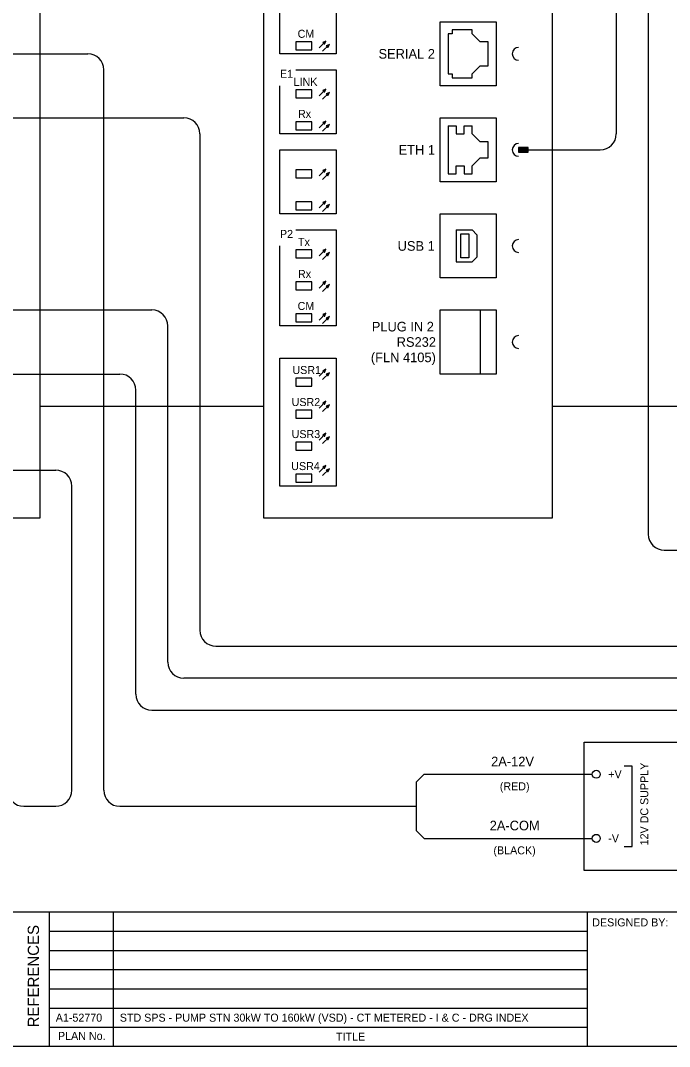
# Model space of a CAD drawing. Extents: x 0 to 841, y 0 to 594.
# Drawn here: x 204 to 406.6, y 15 to 335.4 of the extents above; entities that cross this region are included whole.
import ezdxf

# ---------------------------------------------------------------- set-up
doc = ezdxf.new("R2010")
doc.units = 0
for name, color, linetype in [('A1BORDER', 7, 'Continuous'), ('Level 1', 7, 'Continuous'), ('Level 10', 7, 'Continuous'), ('Level 5', 7, 'Continuous')]:
    doc.layers.add(name, color=color, linetype=linetype)

msp = doc.modelspace()

# ---------------------------------------------------------------- linework, layer by layer
at = {"layer": 'A1BORDER'}
for p, q in [((28, 57), (829, 57)), ((213, 15), (213, 57)), ((233, 15), (233, 57)), ((381, 15), (381, 57)), ((213, 51), (381, 51)), ((213, 45), (381, 45)), ((213, 39), (381, 39)), ((213, 33), (381, 33)), ((213, 27), (381, 27)), ((213, 21), (381, 21)), ((829, 15), (28, 15))]:
    msp.add_line(p, q, dxfattribs=at)
at = {"layer": 'Level 1'}
for p, q in [((390, 560), (390, 300)), ((400, 390), (400, 175)), ((337.5, 331.25), (337.5, 318.75)), ((338.75, 331.25), (337.5, 331.25)), ((345, 332.5), (338.75, 332.5)), ((338.75, 332.5), (338.75, 331.25)), ((345, 331.25), (345, 332.5)), ((345, 331.25), (347.5, 328.75)), ((350, 328.75), (347.5, 328.75)), ((350, 321.25), (350, 328.75)), ((197.5, 325), (225, 325)), ((345, 318.75), (347.5, 321.25)), ((347.5, 321.25), (350, 321.25)), ((230, 95), (230, 320)), ((337.5, 318.75), (338.75, 318.75)), ((338.75, 318.75), (338.75, 317.5)), ((338.75, 317.5), (345, 317.5)), ((345, 317.5), (345, 318.75)), ((197.5, 305), (255, 305)), ((337.5, 302.5), (337.5, 287.5)), ((337.5, 302.5), (340, 302.5)), ((340, 302.5), (340, 300)), ((342.5, 300), (342.5, 302.5)), ((342.5, 302.5), (345, 302.5)), ((345, 300), (345, 302.5)), ((260, 300), (260, 145)), ((340, 300), (342.5, 300)), ((345, 300), (347.5, 297.5)), ((350, 297.5), (347.5, 297.5)), ((350, 292.5), (350, 297.5)), ((362.5, 295), (385, 295)), ((345, 290), (347.5, 292.5)), ((347.5, 292.5), (350, 292.5)), ((340, 287.5), (340, 290)), ((340, 290), (342.5, 290)), ((342.5, 290), (342.5, 287.5)), ((345, 287.5), (345, 290)), ((337.5, 287.5), (340, 287.5)), ((342.5, 287.5), (345, 287.5)), ((340, 270), (340, 260)), ((340, 270), (345, 270)), ((345, 270), (346.5, 268.5)), ((346.5, 268.5), (346.5, 261.5)), ((340, 260), (345, 260)), ((345, 260), (346.5, 261.5)), ((197.5, 245), (245, 245)), ((347.5, 245), (347.5, 225)), ((250, 135), (250, 240)), ((197.5, 225), (235, 225)), ((240, 125), (240, 220)), ((210, 215), (280, 215)), ((370, 215), (410, 215)), ((197.5, 195), (215, 195)), ((220, 95), (220, 190)), ((405, 170), (595, 170)), ((265, 140), (610, 140)), ((645, 130), (255, 130)), ((245, 120), (725, 120)), ((330, 100), (327.5, 97.5)), ((330, 100), (382.5, 100)), ((327.5, 97.5), (327.5, 82.5)), ((205, 90), (215, 90)), ((215, 90), (215, 90)), ((235, 90), (327.51, 90)), ((330, 80), (327.5, 82.5)), ((330, 80), (382.5, 80))]:
    msp.add_line(p, q, dxfattribs=at)
for points in [[(130, 520), (210, 520), (210, 180), (130, 180)], [(280, 520), (370, 520), (370, 180), (280, 180)], [(335, 335), (352.5, 335), (352.5, 315), (335, 315)], [(295, 328.75), (290, 328.75), (290, 326.25), (295, 326.25)], [(295, 313.75), (290, 313.75), (290, 311.25), (295, 311.25)], [(335, 305), (352.5, 305), (352.5, 285), (335, 285)], [(295, 303.75), (290, 303.75), (290, 301.25), (295, 301.25)], [(285, 295), (302.5, 295), (302.5, 275), (285, 275)], [(295, 288.75), (290, 288.75), (290, 286.25), (295, 286.25)], [(295, 278.75), (290, 278.75), (290, 276.25), (295, 276.25)], [(335, 275), (352.5, 275), (352.5, 255), (335, 255)], [(341.5, 268.75), (344, 268.75), (344, 261.25), (341.5, 261.25)], [(295, 263.75), (290, 263.75), (290, 261.25), (295, 261.25)], [(295, 253.75), (290, 253.75), (290, 251.25), (295, 251.25)], [(295, 243.75), (290, 243.75), (290, 241.25), (295, 241.25)], [(335, 245), (352.5, 245), (352.5, 225), (335, 225)], [(285, 230), (302.5, 230), (302.5, 190), (285, 190)], [(295, 223.75), (290, 223.75), (290, 221.25), (295, 221.25)], [(295, 213.75), (290, 213.75), (290, 211.25), (295, 211.25)], [(295, 203.75), (290, 203.75), (290, 201.25), (295, 201.25)], [(295, 193.75), (290, 193.75), (290, 191.25), (295, 191.25)], [(380, 110), (455, 110), (455, 70), (380, 70)]]:
    msp.add_lwpolyline(points, close=True, dxfattribs=at)
for points in [[(290, 355), (302.5, 355), (302.5, 325), (285, 325), (285, 350)], [(290, 320), (302.5, 320), (302.5, 300), (285, 300), (285, 315)], [(290, 270), (302.5, 270), (302.5, 240), (285, 240), (285, 265)], [(392.5, 77.5), (395, 77.5), (395, 102.5), (392.5, 102.5)]]:
    msp.add_lwpolyline(points, dxfattribs=at)
for centre, start, end in [((225, 320), 0, 90), ((255, 300), 0, 90), ((385, 300), 270, 0), ((245, 240), 0, 90), ((235, 220), 0, 90), ((215, 190), 0, 90), ((405, 175), 180, 270), ((265, 145), 180, 270), ((255, 135), 180, 270), ((245, 125), 180, 270), ((205, 95), 180, 270), ((215, 95), 270, 360), ((235, 95), 180, 270)]:
    msp.add_arc(centre, 5, start, end, dxfattribs=at)
at = {"layer": 'Level 10'}
for p, q in [((297.23, 326.86), (299.36, 328.98)), ((298.29, 325.8), (300.42, 327.92)), ((298.46, 328.57), (299.17, 328.57)), ((298.5, 328.43), (299.11, 328.43)), ((298.64, 328.28), (299.04, 328.28)), ((298.79, 328.73), (299.24, 328.73)), ((298.8, 328.12), (298.97, 328.12)), ((299.12, 328.88), (299.31, 328.88)), ((299.52, 327.51), (300.23, 327.51)), ((299.56, 327.37), (300.17, 327.37)), ((299.7, 327.22), (300.1, 327.22)), ((299.85, 327.67), (300.3, 327.67)), ((299.86, 327.06), (300.03, 327.06)), ((300.18, 327.81), (300.37, 327.81)), ((297.23, 311.86), (299.36, 313.98)), ((298.29, 310.8), (300.42, 312.92)), ((298.46, 313.57), (299.17, 313.57)), ((298.5, 313.43), (299.11, 313.43)), ((298.64, 313.28), (299.04, 313.28)), ((298.79, 313.73), (299.24, 313.73)), ((298.8, 313.12), (298.97, 313.12)), ((299.12, 313.88), (299.31, 313.88)), ((299.52, 312.51), (300.23, 312.51)), ((299.56, 312.37), (300.17, 312.37)), ((299.7, 312.22), (300.1, 312.22)), ((299.85, 312.67), (300.3, 312.67)), ((299.86, 312.06), (300.03, 312.06)), ((300.18, 312.81), (300.37, 312.81)), ((297.23, 301.86), (299.36, 303.98)), ((298.29, 300.8), (300.42, 302.92)), ((298.46, 303.57), (299.17, 303.57)), ((298.5, 303.43), (299.11, 303.43)), ((298.64, 303.28), (299.04, 303.28)), ((298.79, 303.73), (299.24, 303.73)), ((298.8, 303.12), (298.97, 303.12)), ((299.12, 303.88), (299.31, 303.88)), ((299.52, 302.51), (300.23, 302.51)), ((299.56, 302.37), (300.17, 302.37)), ((299.7, 302.22), (300.1, 302.22)), ((299.85, 302.67), (300.3, 302.67)), ((299.86, 302.06), (300.03, 302.06)), ((300.18, 302.81), (300.37, 302.81)), ((359.5, 295.5), (362.5, 295.5)), ((359.5, 295.25), (362.5, 295.25)), ((359.5, 295), (362.5, 295)), ((359.5, 294.75), (362.5, 294.75)), ((359.5, 294.5), (362.5, 294.5)), ((297.23, 286.86), (299.36, 288.98)), ((298.46, 288.57), (299.17, 288.57)), ((298.5, 288.43), (299.11, 288.43)), ((298.79, 288.73), (299.24, 288.73)), ((299.12, 288.88), (299.31, 288.88)), ((298.29, 285.8), (300.42, 287.92)), ((298.64, 288.28), (299.04, 288.28)), ((298.8, 288.12), (298.97, 288.12)), ((299.52, 287.51), (300.23, 287.51)), ((299.56, 287.37), (300.17, 287.37)), ((299.7, 287.22), (300.1, 287.22)), ((299.85, 287.67), (300.3, 287.67)), ((299.86, 287.06), (300.03, 287.06)), ((300.18, 287.81), (300.37, 287.81)), ((297.23, 276.86), (299.36, 278.98)), ((299.12, 278.88), (299.31, 278.88)), ((298.29, 275.8), (300.42, 277.92)), ((298.46, 278.57), (299.17, 278.57)), ((298.5, 278.43), (299.11, 278.43)), ((298.64, 278.28), (299.04, 278.28)), ((298.79, 278.73), (299.24, 278.73)), ((298.8, 278.12), (298.97, 278.12)), ((299.52, 277.51), (300.23, 277.51)), ((299.56, 277.37), (300.17, 277.37)), ((299.7, 277.22), (300.1, 277.22)), ((299.85, 277.67), (300.3, 277.67)), ((299.86, 277.06), (300.03, 277.06)), ((300.18, 277.81), (300.37, 277.81)), ((297.23, 261.86), (299.36, 263.98)), ((298.29, 260.8), (300.42, 262.92)), ((298.46, 263.57), (299.17, 263.57)), ((298.5, 263.43), (299.11, 263.43)), ((298.64, 263.27), (299.04, 263.27)), ((298.79, 263.73), (299.24, 263.73)), ((298.8, 263.12), (298.97, 263.12)), ((299.12, 263.88), (299.31, 263.88)), ((300.18, 262.81), (300.37, 262.81)), ((299.52, 262.51), (300.23, 262.51)), ((299.56, 262.37), (300.17, 262.37)), ((299.7, 262.22), (300.1, 262.22)), ((299.85, 262.67), (300.3, 262.67)), ((299.86, 262.06), (300.03, 262.06)), ((297.23, 251.86), (299.36, 253.98)), ((298.46, 253.58), (299.17, 253.58)), ((298.5, 253.43), (299.11, 253.43)), ((298.64, 253.28), (299.04, 253.28)), ((298.79, 253.72), (299.24, 253.72)), ((298.8, 253.12), (298.97, 253.12)), ((299.12, 253.88), (299.31, 253.88)), ((298.29, 250.8), (300.42, 252.92)), ((299.52, 252.52), (300.23, 252.52)), ((299.56, 252.37), (300.17, 252.37)), ((299.7, 252.22), (300.1, 252.22)), ((299.85, 252.66), (300.3, 252.66)), ((299.86, 252.06), (300.03, 252.06)), ((300.18, 252.81), (300.37, 252.81)), ((297.23, 241.86), (299.36, 243.98)), ((298.46, 243.58), (299.17, 243.58)), ((298.79, 243.72), (299.24, 243.72)), ((299.12, 243.88), (299.31, 243.88)), ((298.29, 240.8), (300.42, 242.92)), ((298.5, 243.43), (299.11, 243.43)), ((298.64, 243.28), (299.04, 243.28)), ((298.8, 243.12), (298.97, 243.12)), ((299.52, 242.52), (300.23, 242.52)), ((299.56, 242.37), (300.17, 242.37)), ((299.7, 242.22), (300.1, 242.22)), ((299.85, 242.66), (300.3, 242.66)), ((299.86, 242.06), (300.03, 242.06)), ((300.18, 242.81), (300.37, 242.81)), ((297.23, 224.36), (299.36, 226.48)), ((298.29, 223.3), (300.42, 225.42)), ((298.46, 226.08), (299.17, 226.08)), ((298.5, 225.93), (299.11, 225.93)), ((298.64, 225.78), (299.04, 225.78)), ((298.79, 226.22), (299.24, 226.22)), ((298.8, 225.62), (298.97, 225.62)), ((299.12, 226.38), (299.31, 226.38)), ((299.52, 225.02), (300.23, 225.02)), ((299.56, 224.87), (300.17, 224.87)), ((299.7, 224.72), (300.1, 224.72)), ((299.85, 225.16), (300.3, 225.16)), ((299.86, 224.56), (300.03, 224.56)), ((300.18, 225.31), (300.37, 225.31)), ((297.23, 214.36), (299.36, 216.48)), ((298.29, 213.3), (300.42, 215.42)), ((298.46, 216.08), (299.17, 216.08)), ((298.5, 215.93), (299.11, 215.93)), ((298.64, 215.78), (299.04, 215.78)), ((298.79, 216.22), (299.24, 216.22)), ((298.8, 215.62), (298.97, 215.62)), ((299.12, 216.38), (299.31, 216.38)), ((299.52, 215.02), (300.23, 215.02)), ((299.56, 214.87), (300.17, 214.87)), ((299.7, 214.72), (300.1, 214.72)), ((299.85, 215.16), (300.3, 215.16)), ((300.18, 215.31), (300.37, 215.31)), ((299.86, 214.56), (300.03, 214.56)), ((297.23, 204.36), (299.36, 206.48)), ((298.29, 203.3), (300.42, 205.42)), ((298.46, 206.08), (299.17, 206.08)), ((298.5, 205.93), (299.11, 205.93)), ((298.64, 205.78), (299.04, 205.78)), ((298.79, 206.22), (299.24, 206.22)), ((298.8, 205.62), (298.97, 205.62)), ((299.12, 206.38), (299.31, 206.38)), ((299.85, 205.16), (300.3, 205.16)), ((300.18, 205.31), (300.37, 205.31)), ((299.52, 205.02), (300.23, 205.02)), ((299.56, 204.87), (300.17, 204.87)), ((299.7, 204.72), (300.1, 204.72)), ((299.86, 204.56), (300.03, 204.56)), ((297.23, 194.36), (299.36, 196.48)), ((298.46, 196.08), (299.17, 196.08)), ((298.5, 195.93), (299.11, 195.93)), ((298.64, 195.78), (299.04, 195.78)), ((298.79, 196.22), (299.24, 196.22)), ((298.8, 195.62), (298.97, 195.62)), ((299.12, 196.38), (299.31, 196.38)), ((298.29, 193.3), (300.42, 195.42)), ((299.52, 195.02), (300.23, 195.02)), ((299.56, 194.87), (300.17, 194.87)), ((299.7, 194.72), (300.1, 194.72)), ((299.85, 195.16), (300.3, 195.16)), ((299.86, 194.56), (300.03, 194.56)), ((300.18, 195.31), (300.37, 195.31))]:
    msp.add_line(p, q, dxfattribs=at)
for points in [[(299.36, 328.98), (298.38, 328.54), (298.92, 328)], [(300.42, 327.92), (299.44, 327.48), (299.98, 326.94)], [(299.36, 313.98), (298.38, 313.54), (298.92, 313)], [(300.42, 312.92), (299.44, 312.48), (299.98, 311.94)], [(299.36, 303.98), (298.38, 303.54), (298.92, 303)], [(300.42, 302.92), (299.44, 302.48), (299.98, 301.94)], [(359.5, 294.25), (362.5, 294.25), (362.5, 295.75), (359.5, 295.75)], [(299.36, 288.98), (298.38, 288.54), (298.92, 288)], [(300.42, 287.92), (299.44, 287.48), (299.98, 286.94)], [(299.36, 278.98), (298.38, 278.54), (298.92, 278)], [(300.42, 277.92), (299.44, 277.48), (299.98, 276.94)], [(299.36, 263.98), (298.38, 263.54), (298.92, 263)], [(300.42, 262.92), (299.44, 262.48), (299.98, 261.94)], [(299.36, 253.98), (298.38, 253.54), (298.92, 253)], [(300.42, 252.92), (299.44, 252.48), (299.98, 251.94)], [(299.36, 243.98), (298.38, 243.54), (298.92, 243)], [(300.42, 242.92), (299.44, 242.48), (299.98, 241.94)], [(299.36, 226.48), (298.38, 226.04), (298.92, 225.5)], [(300.42, 225.42), (299.44, 224.98), (299.98, 224.44)], [(299.36, 216.48), (298.38, 216.04), (298.92, 215.5)], [(300.42, 215.42), (299.44, 214.98), (299.98, 214.44)], [(299.36, 206.48), (298.38, 206.04), (298.92, 205.5)], [(300.42, 205.42), (299.44, 204.98), (299.98, 204.44)], [(299.36, 196.48), (298.38, 196.04), (298.92, 195.5)], [(300.42, 195.42), (299.44, 194.98), (299.98, 194.44)]]:
    msp.add_lwpolyline(points, close=True, dxfattribs=at)
for centre in [(383.75, 100), (383.75, 80)]:
    msp.add_circle(centre, 1.25, dxfattribs=at)
for centre in [(359.5, 325), (359.5, 295), (359.5, 265), (359.5, 235)]:
    msp.add_arc(centre, 2, 90, 270, dxfattribs=at)

# ---------------------------------------------------------------- texts
at = {"layer": 'A1BORDER'}
for s, p in [('DESIGNED BY:', (382.5, 52.5)), ('PLAN No.', (215.69, 17.06)), ('TITLE', (302.5, 16.81))]:
    msp.add_text(s, height=2.5, dxfattribs=at).set_placement(p)
msp.add_text('REFERENCES', height=3.5, rotation=90, dxfattribs=at).set_placement((209.76, 20.96))
at = {"layer": 'Level 1'}
for s, height, p in [('CM', 2.5, (290.51, 330)), ('SERIAL 2', 3, (315.77, 323.5)), ('E1', 2.5, (285, 317.5)), ('LINK', 2.5, (289.26, 315)), ('Rx', 2.5, (290.63, 305)), ('ETH 1', 3, (322.04, 293.5)), ('P2', 2.5, (285, 267.5)), ('Tx', 2.5, (290.63, 265)), ('USB 1', 3, (321.74, 263.5)), ('Rx', 2.5, (290.63, 255)), ('CM', 2.5, (290.51, 245)), ('PLUG IN 2', 3, (313.67, 238.3)), ('RS232', 3, (321.44, 233.5)), ('(FLN 4105)', 3, (313.38, 228.7)), ('USR1', 2.5, (288.89, 225)), ('USR2', 2.5, (288.64, 215)), ('USR3', 2.5, (288.64, 205)), ('USR4', 2.5, (288.52, 195)), ('2A-12V', 3, (350.93, 102.5)), ('+V', 2.5, (387.5, 98.75)), ('2A-COM', 3, (350.48, 82.5)), ('-V', 2.5, (387.5, 78.75)), ('A1-52770', 2.5, (215, 22.75)), ('STD SPS - PUMP STN 30kW TO 160kW (VSD) - CT METERED - I & C - DRG INDEX', 2.5, (235, 22.75))]:
    msp.add_text(s, height=height, dxfattribs=at).set_placement(p)
at = {"layer": 'Level 5'}
msp.add_text('12V DC SUPPLY', height=2.5, rotation=90, dxfattribs=at).set_placement((400, 77.8))
for s, p in [('(RED)', (353.64, 95)), ('(BLACK)', (351.65, 75))]:
    msp.add_text(s, height=2.5, dxfattribs=at).set_placement(p)

doc.saveas('drawing.dxf')
